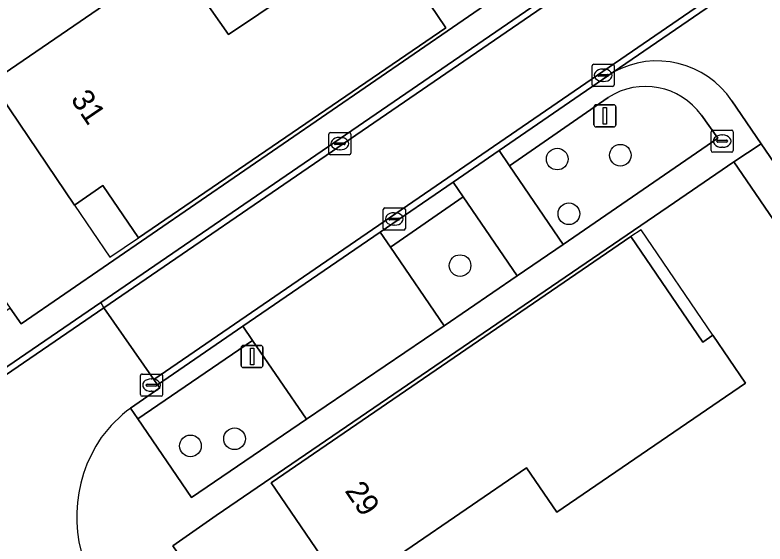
# Model space of a CAD drawing. Extents: x 155275 to 156265, y 382654 to 383635.
# Drawn here: x 155596.86 to 155630.71, y 383396.14 to 383420.02 of the extents above; entities that cross this region are included whole.
import ezdxf

# ---------------------------------------------------------------- set-up
doc = ezdxf.new("R2010")
doc.units = 0
for name, color, linetype in [('IMGEO_Boom', 7, 'Continuous'), ('IMGEO_Brandkraan', 7, 'Continuous'), ('IMGEO_Erf', 7, 'Continuous'), ('IMGEO_Groenvoorziening', 7, 'Continuous'), ('IMGEO_Kolk', 7, 'Continuous'), ('IMGEO_Lichtmast', 7, 'Continuous'), ('IMGEO_Pand', 7, 'Continuous'), ('IMGEO_Pand_nummerreeks', 7, 'Continuous'), ('IMGEO_Pand_overbouw', 7, 'Continuous'), ('IMGEO_Parkeervlak_open', 7, 'Continuous'), ('IMGEO_Rijbaan_lokaal_open', 7, 'Continuous'), ('IMGEO_Voetpad_open', 7, 'Continuous')]:
    doc.layers.add(name, color=color, linetype=linetype)

msp = doc.modelspace()

# ---------------------------------------------------------------- linework, layer by layer
at = {"layer": 'IMGEO_Boom'}
for centre in [(155621.331, 383413.517), (155624.18, 383413.689), (155621.856, 383411.046), (155616.944, 383408.707), (155606.769, 383400.892), (155604.777, 383400.572)]:
    msp.add_circle(centre, 0.489, dxfattribs=at)
at = {"layer": 'IMGEO_Brandkraan'}
for p, q in [((155628.278, 383413.9), (155628.278, 383414.752)), ((155628.353, 383414.826), (155629.205, 383414.826)), ((155628.766, 383414.606), (155628.791, 383414.606)), ((155629.279, 383414.752), (155629.279, 383413.9)), ((155628.537, 383414.32), (155628.537, 383414.332)), ((155628.975, 383414.283), (155628.577, 383414.283)), ((155628.58, 383414.369), (155628.978, 383414.369)), ((155629.021, 383414.332), (155629.021, 383414.32)), ((155628.789, 383414.046), (155628.764, 383414.046)), ((155629.205, 383413.826), (155628.353, 383413.826))]:
    msp.add_line(p, q, dxfattribs=at)
for points in [[(155628.278, 383413.9), (155628.278, 383414.752)], [(155628.353, 383414.826), (155629.205, 383414.826)], [(155629.279, 383414.752), (155629.279, 383413.9)], [(155629.205, 383413.826), (155628.353, 383413.826)]]:
    msp.add_lwpolyline(points, dxfattribs=at)
for centre, radius, start, end in [((155628.355, 383414.75), 0.0765, 91.552, 178.448), ((155628.355, 383414.75), 0.0765, 91.552, 178.448), ((155629.203, 383414.75), 0.0765, 1.552, 88.448), ((155629.203, 383414.75), 0.0765, 1.552, 88.448), ((155628.577, 383414.329), 0.0403, 85.8775, 175.7526), ((155628.574, 383414.319), 0.0366, 178.938, 274.7102), ((155628.978, 383414.326), 0.043, 264.8664, 352.4533), ((155628.982, 383414.331), 0.0386, 1.7309, 96.639), ((155628.355, 383413.902), 0.0765, 181.552, 268.448), ((155628.355, 383413.902), 0.0765, 181.552, 268.448), ((155629.203, 383413.902), 0.0765, 271.552, 358.448), ((155629.203, 383413.902), 0.0765, 271.552, 358.448)]:
    msp.add_arc(centre, radius, start, end, dxfattribs=at)
for centre, major_axis, ratio, start_param, end_param in [((155628.765, 383414.326), (-0.387, 0.002), 0.722429, 4.712389, 7.853982), ((155628.79, 383414.326), (-0.39, 0.002), 0.717154, 1.570796, 4.712389)]:
    msp.add_ellipse(centre, major_axis=major_axis, ratio=ratio, start_param=start_param, end_param=end_param, dxfattribs=at)
at = {"layer": 'IMGEO_Erf'}
msp.add_lwpolyline([(155564.638, 383453.515), (155596.013, 383407.669), (155596.635, 383406.788), (155597.134, 383406.082), (155620.785, 383422.343), (155620.822, 383422.366)], dxfattribs=at)
for points in [[(155613.378, 383423.777), (155616.308, 383419.439), (155602.425, 383409.959), (155600.821, 383412.324), (155599.544, 383411.437), (155595.775, 383416.983), (155604.037, 383422.635), (155606.5, 383419.132)], [(155626.344, 383411.364), (155605.932, 383397.438), (155603.987, 383396.057), (155605.754, 383393.471), (155605.827, 383393.52), (155653.992, 383322.86), (155654.882, 383321.57), (155677.497, 383337.038), (155680.25, 383338.906), (155654.839, 383376.063), (155629.299, 383413.395)], [(155621.307, 383397.58), (155619.94, 383399.584), (155611.775, 383393.983), (155608.422, 383398.907), (155624.655, 383410.016), (155627.904, 383405.256), (155628.359, 383405.565), (155629.83, 383403.396)]]:
    msp.add_lwpolyline(points, close=True, dxfattribs=at)
at = {"layer": 'IMGEO_Groenvoorziening'}
for points in [[(155623.631, 383416.297), (155619.174, 383413.216)], [(155619.174, 383413.216), (155621.598, 383409.66), (155628.573, 383414.458), (155627.843, 383415.49)]]:
    msp.add_lwpolyline(points, dxfattribs=at)
for points in [[(155617.085, 383411.817), (155613.806, 383409.546), (155616.23, 383405.989), (155619.517, 383408.243)], [(155610.01, 383401.784), (155607.579, 383405.331), (155602.405, 383401.798), (155604.822, 383398.241)]]:
    msp.add_lwpolyline(points, close=True, dxfattribs=at)
msp.add_arc((155625.315, 383413.689), 3.104, 35.4642, 122.8434, dxfattribs=at)
at = {"layer": 'IMGEO_Kolk'}
for p, q in [((155622.902, 383416.87), (155622.902, 383417.722)), ((155622.977, 383417.796), (155623.829, 383417.796)), ((155623.903, 383417.722), (155623.903, 383416.87)), ((155623.161, 383417.29), (155623.161, 383417.302)), ((155623.599, 383417.253), (155623.201, 383417.253)), ((155623.204, 383417.339), (155623.602, 383417.339)), ((155623.39, 383417.576), (155623.415, 383417.576)), ((155623.645, 383417.302), (155623.645, 383417.29)), ((155623.413, 383417.016), (155623.388, 383417.016)), ((155623.829, 383416.796), (155622.977, 383416.796)), ((155611.016, 383413.786), (155611.016, 383414.638)), ((155611.091, 383414.712), (155611.943, 383414.712)), ((155612.017, 383414.638), (155612.017, 383413.786)), ((155611.275, 383414.206), (155611.275, 383414.218)), ((155611.318, 383414.255), (155611.716, 383414.255)), ((155611.504, 383414.492), (155611.529, 383414.492)), ((155611.759, 383414.218), (155611.759, 383414.206)), ((155611.713, 383414.169), (155611.315, 383414.169)), ((155611.527, 383413.932), (155611.502, 383413.932)), ((155611.943, 383413.712), (155611.091, 383413.712)), ((155613.475, 383410.386), (155613.475, 383411.238)), ((155613.55, 383411.312), (155614.402, 383411.312)), ((155614.476, 383411.238), (155614.476, 383410.386)), ((155613.777, 383410.855), (155614.175, 383410.855)), ((155613.963, 383411.092), (155613.988, 383411.092)), ((155613.734, 383410.806), (155613.734, 383410.818)), ((155614.172, 383410.769), (155613.774, 383410.769)), ((155613.986, 383410.532), (155613.961, 383410.532)), ((155614.218, 383410.818), (155614.218, 383410.806)), ((155614.402, 383410.312), (155613.55, 383410.312)), ((155602.521, 383402.89), (155602.521, 383403.742)), ((155602.596, 383403.816), (155603.448, 383403.816)), ((155603.522, 383403.742), (155603.522, 383402.89)), ((155603.009, 383403.596), (155603.034, 383403.596)), ((155602.78, 383403.31), (155602.78, 383403.322)), ((155603.218, 383403.273), (155602.82, 383403.273)), ((155602.823, 383403.359), (155603.221, 383403.359)), ((155603.032, 383403.036), (155603.007, 383403.036)), ((155603.264, 383403.322), (155603.264, 383403.31)), ((155603.448, 383402.816), (155602.596, 383402.816))]:
    msp.add_line(p, q, dxfattribs=at)
for points in [[(155622.902, 383416.87), (155622.902, 383417.722)], [(155622.977, 383417.796), (155623.829, 383417.796)], [(155623.903, 383417.722), (155623.903, 383416.87)], [(155623.829, 383416.796), (155622.977, 383416.796)], [(155611.016, 383413.786), (155611.016, 383414.638)], [(155611.091, 383414.712), (155611.943, 383414.712)], [(155612.017, 383414.638), (155612.017, 383413.786)], [(155611.943, 383413.712), (155611.091, 383413.712)], [(155613.475, 383410.386), (155613.475, 383411.238)], [(155613.55, 383411.312), (155614.402, 383411.312)], [(155614.476, 383411.238), (155614.476, 383410.386)], [(155614.402, 383410.312), (155613.55, 383410.312)], [(155602.521, 383402.89), (155602.521, 383403.742)], [(155602.596, 383403.816), (155603.448, 383403.816)], [(155603.522, 383403.742), (155603.522, 383402.89)], [(155603.448, 383402.816), (155602.596, 383402.816)]]:
    msp.add_lwpolyline(points, dxfattribs=at)
for centre, radius, start, end in [((155622.979, 383417.72), 0.0765, 91.552, 178.448), ((155622.979, 383417.72), 0.0765, 91.552, 178.448), ((155623.827, 383417.72), 0.0765, 1.552, 88.448), ((155623.827, 383417.72), 0.0765, 1.552, 88.448), ((155623.201, 383417.299), 0.0403, 85.8775, 175.7526), ((155623.198, 383417.289), 0.0366, 178.938, 274.7102), ((155623.602, 383417.296), 0.043, 264.8664, 352.4533), ((155623.606, 383417.301), 0.0386, 1.7309, 96.639), ((155622.979, 383416.872), 0.0765, 181.552, 268.448), ((155622.979, 383416.872), 0.0765, 181.552, 268.448), ((155623.827, 383416.872), 0.0765, 271.552, 358.448), ((155623.827, 383416.872), 0.0765, 271.552, 358.448), ((155611.093, 383414.636), 0.0765, 91.552, 178.448), ((155611.093, 383414.636), 0.0765, 91.552, 178.448), ((155611.941, 383414.636), 0.0765, 1.552, 88.448), ((155611.941, 383414.636), 0.0765, 1.552, 88.448), ((155611.315, 383414.215), 0.0403, 85.8775, 175.7526), ((155611.312, 383414.205), 0.0366, 178.938, 274.7102), ((155611.716, 383414.212), 0.043, 264.8664, 352.4533), ((155611.72, 383414.217), 0.0386, 1.7309, 96.639), ((155611.093, 383413.788), 0.0765, 181.552, 268.448), ((155611.093, 383413.788), 0.0765, 181.552, 268.448), ((155611.941, 383413.788), 0.0765, 271.552, 358.448), ((155611.941, 383413.788), 0.0765, 271.552, 358.448), ((155613.552, 383411.236), 0.0765, 91.552, 178.448), ((155613.552, 383411.236), 0.0765, 91.552, 178.448), ((155614.4, 383411.236), 0.0765, 1.552, 88.448), ((155614.4, 383411.236), 0.0765, 1.552, 88.448), ((155613.774, 383410.815), 0.0403, 85.8775, 175.7526), ((155614.179, 383410.817), 0.0386, 1.7309, 96.639), ((155613.771, 383410.805), 0.0366, 178.938, 274.7102), ((155614.175, 383410.812), 0.043, 264.8664, 352.4533), ((155613.552, 383410.388), 0.0765, 181.552, 268.448), ((155613.552, 383410.388), 0.0765, 181.552, 268.448), ((155614.4, 383410.388), 0.0765, 271.552, 358.448), ((155614.4, 383410.388), 0.0765, 271.552, 358.448), ((155602.598, 383403.74), 0.0765, 91.552, 178.448), ((155602.598, 383403.74), 0.0765, 91.552, 178.448), ((155603.446, 383403.74), 0.0765, 1.552, 88.448), ((155603.446, 383403.74), 0.0765, 1.552, 88.448), ((155602.82, 383403.319), 0.0403, 85.8775, 175.7526), ((155602.817, 383403.309), 0.0366, 178.938, 274.7102), ((155603.221, 383403.316), 0.043, 264.8664, 352.4533), ((155603.225, 383403.321), 0.0386, 1.7309, 96.639), ((155602.598, 383402.892), 0.0765, 181.552, 268.448), ((155602.598, 383402.892), 0.0765, 181.552, 268.448), ((155603.446, 383402.892), 0.0765, 271.552, 358.448), ((155603.446, 383402.892), 0.0765, 271.552, 358.448)]:
    msp.add_arc(centre, radius, start, end, dxfattribs=at)
for centre, major_axis, ratio, start_param, end_param in [((155623.389, 383417.296), (-0.387, 0.002), 0.722429, 4.712389, 7.853982), ((155623.414, 383417.296), (-0.39, 0.002), 0.717154, 1.570796, 4.712389), ((155611.503, 383414.212), (-0.387, 0.002), 0.722429, 4.712389, 7.853982), ((155611.528, 383414.212), (-0.39, 0.002), 0.717154, 1.570796, 4.712389), ((155613.962, 383410.812), (-0.387, 0.002), 0.722429, 4.712389, 7.853982), ((155613.987, 383410.812), (-0.39, 0.002), 0.717154, 1.570796, 4.712389), ((155603.008, 383403.316), (-0.387, 0.002), 0.722429, 4.712389, 7.853982), ((155603.033, 383403.316), (-0.39, 0.002), 0.717154, 1.570796, 4.712389)]:
    msp.add_ellipse(centre, major_axis=major_axis, ratio=ratio, start_param=start_param, end_param=end_param, dxfattribs=at)
at = {"layer": 'IMGEO_Lichtmast'}
for p, q in [((155623.088, 383415.968), (155623.878, 383415.968)), ((155623.878, 383415.968), (155623.088, 383415.968)), ((155622.988, 383415.068), (155622.988, 383415.868)), ((155622.988, 383415.868), (155622.988, 383415.068)), ((155623.978, 383415.868), (155623.978, 383415.068)), ((155623.978, 383415.068), (155623.978, 383415.868)), ((155623.878, 383414.968), (155623.088, 383414.968)), ((155623.088, 383414.968), (155623.878, 383414.968)), ((155607.16, 383405.106), (155607.95, 383405.106)), ((155607.95, 383405.106), (155607.16, 383405.106)), ((155607.06, 383404.206), (155607.06, 383405.006)), ((155607.06, 383405.006), (155607.06, 383404.206)), ((155608.05, 383405.006), (155608.05, 383404.206)), ((155608.05, 383404.206), (155608.05, 383405.006)), ((155607.95, 383404.106), (155607.16, 383404.106)), ((155607.16, 383404.106), (155607.95, 383404.106))]:
    msp.add_line(p, q, dxfattribs=at)
for points in [[(155623.408, 383415.843), (155623.558, 383415.843), (155623.558, 383415.093), (155623.408, 383415.093), (155623.408, 383415.843)], [(155607.48, 383404.981), (155607.63, 383404.981), (155607.63, 383404.231), (155607.48, 383404.231), (155607.48, 383404.981)]]:
    msp.add_lwpolyline(points, dxfattribs=at)
for centre, start, end in [((155623.088, 383415.868), 90, 180), ((155623.088, 383415.868), 90, 180), ((155623.878, 383415.868), 0, 90), ((155623.878, 383415.868), 360, 90), ((155623.088, 383415.068), 180, 270), ((155623.088, 383415.068), 180, 270), ((155623.878, 383415.068), 270, 0), ((155623.878, 383415.068), 270, 0), ((155607.16, 383405.006), 90, 180), ((155607.16, 383405.006), 90, 180), ((155607.95, 383405.006), 0, 90), ((155607.95, 383405.006), 360, 90), ((155607.16, 383404.206), 180, 270), ((155607.16, 383404.206), 180, 270), ((155607.95, 383404.206), 270, 0), ((155607.95, 383404.206), 270, 0)]:
    msp.add_arc(centre, 0.1, start, end, dxfattribs=at)
at = {"layer": 'IMGEO_Pand'}
for points in [[(155613.378, 383423.777), (155606.5, 383419.132), (155604.037, 383422.635), (155595.775, 383416.983), (155599.544, 383411.437), (155600.821, 383412.324), (155602.425, 383409.959), (155616.308, 383419.439)], [(155624.655, 383410.016), (155608.422, 383398.907), (155611.775, 383393.983), (155619.94, 383399.584), (155621.307, 383397.58), (155629.83, 383403.396), (155628.359, 383405.565), (155627.904, 383405.256)]]:
    msp.add_lwpolyline(points, close=True, dxfattribs=at)
at = {"layer": 'IMGEO_Pand_overbouw'}
for points in [[(155602.425, 383409.959), (155600.821, 383412.324), (155599.544, 383411.437), (155601.132, 383409.088)], [(155624.655, 383410.016), (155627.904, 383405.256), (155628.359, 383405.565), (155625.125, 383410.326)]]:
    msp.add_lwpolyline(points, close=True, dxfattribs=at)
at = {"layer": 'IMGEO_Parkeervlak_open'}
for points in [[(155619.174, 383413.216), (155618.708, 383413.9), (155616.635, 383412.479), (155617.085, 383411.817), (155619.517, 383408.243), (155621.598, 383409.66)], [(155613.806, 383409.546), (155613.345, 383410.223), (155607.142, 383405.969), (155607.579, 383405.331), (155610.01, 383401.784), (155616.23, 383405.989)]]:
    msp.add_lwpolyline(points, close=True, dxfattribs=at)
at = {"layer": 'IMGEO_Rijbaan_lokaal_open'}
for points in [[(155719.204, 383487.735), (155719.05, 383487.959), (155694.212, 383471.066), (155691.045, 383468.901), (155681.838, 383462.606), (155655.747, 383444.77), (155630.619, 383427.541), (155621.24, 383421.11), (155600.732, 383407.049), (155600.872, 383406.808), (155655.916, 383444.522), (155694.436, 383470.854)], [(155658.271, 383441.395), (155696.637, 383467.612), (155721.44, 383484.524), (155719.204, 383487.735), (155694.436, 383470.854), (155655.916, 383444.522), (155600.872, 383406.808), (155603.126, 383403.562)]]:
    msp.add_lwpolyline(points, close=True, dxfattribs=at)
for points in [[(155658.271, 383441.395), (155603.126, 383403.562), (155603.291, 383403.328), (155607.142, 383405.969), (155613.345, 383410.223), (155616.635, 383412.479), (155618.708, 383413.9), (155623.861, 383417.434), (155633.112, 383423.778)], [(155633.112, 383423.778), (155623.861, 383417.434)], [(155629.214, 383416.139), (155630.534, 383414.209), (155681.461, 383339.737), (155682.726, 383337.887)], [(155545.973, 383369.225), (155600.872, 383406.808), (155600.732, 383407.049), (155583.028, 383394.932), (155580.501, 383393.203), (155517.529, 383350.104)], [(155602.078, 383402.28), (155603.392, 383403.185), (155603.291, 383403.328), (155603.126, 383403.562), (155600.872, 383406.808), (155545.973, 383369.225), (155548.143, 383365.998), (155549.095, 383366.65), (155549.258, 383366.407)]]:
    msp.add_lwpolyline(points, dxfattribs=at)
for centre, radius, start, end in [((155625.834, 383413.879), 4.066, 33.7739, 119.0266), ((155606.061, 383396.983), 6.627, 126.94, 143.2326), ((155605.939, 383397.38), 6.297, 145.4603, 211.0622)]:
    msp.add_arc(centre, radius, start, end, dxfattribs=at)
at = {"layer": 'IMGEO_Voetpad_open'}
for points in [[(155622.761, 383423.605), (155620.822, 383422.366), (155620.785, 383422.343), (155597.134, 383406.082), (155596.635, 383406.788), (155594.706, 383405.442), (155594.125, 383405.046), (155581.886, 383396.704), (155583.028, 383394.932), (155600.732, 383407.049), (155621.24, 383421.11)], [(155623.861, 383417.434), (155618.708, 383413.9), (155619.174, 383413.216), (155623.631, 383416.297)], [(155626.344, 383411.364), (155629.299, 383413.395), (155630.534, 383414.209), (155629.214, 383416.139)], [(155627.843, 383415.49), (155628.573, 383414.458), (155621.598, 383409.66), (155619.517, 383408.243), (155616.23, 383405.989), (155610.01, 383401.784), (155604.822, 383398.241), (155602.405, 383401.798), (155602.078, 383402.28)], [(155600.545, 383394.131), (155602.488, 383391.286), (155603.776, 383392.148), (155605.754, 383393.471), (155603.987, 383396.057), (155605.932, 383397.438), (155626.344, 383411.364)]]:
    msp.add_lwpolyline(points, dxfattribs=at)
for points in [[(155630.534, 383414.209), (155629.299, 383413.395), (155654.839, 383376.063), (155680.25, 383338.906), (155681.461, 383339.737)], [(155617.085, 383411.817), (155616.635, 383412.479), (155613.345, 383410.223), (155613.806, 383409.546)], [(155607.579, 383405.331), (155607.142, 383405.969), (155603.291, 383403.328), (155603.392, 383403.185), (155602.078, 383402.28), (155602.405, 383401.798)]]:
    msp.add_lwpolyline(points, close=True, dxfattribs=at)
for centre, radius, start, end in [((155625.834, 383413.879), 4.066, 33.7739, 119.0266), ((155625.315, 383413.689), 3.104, 35.4642, 122.8434), ((155606.061, 383396.983), 6.627, 126.94, 143.2326), ((155605.939, 383397.38), 6.297, 145.4603, 211.0622)]:
    msp.add_arc(centre, radius, start, end, dxfattribs=at)

# ---------------------------------------------------------------- texts
at = {"layer": 'IMGEO_Pand_nummerreeks'}
for s, rotation, p in [('31', 304.1981, (155599.343, 383416.216)), ('29', 304.2504, (155611.717, 383398.546))]:
    msp.add_text(s, height=1, rotation=rotation, dxfattribs=at).set_placement(p)

doc.saveas('drawing.dxf')
